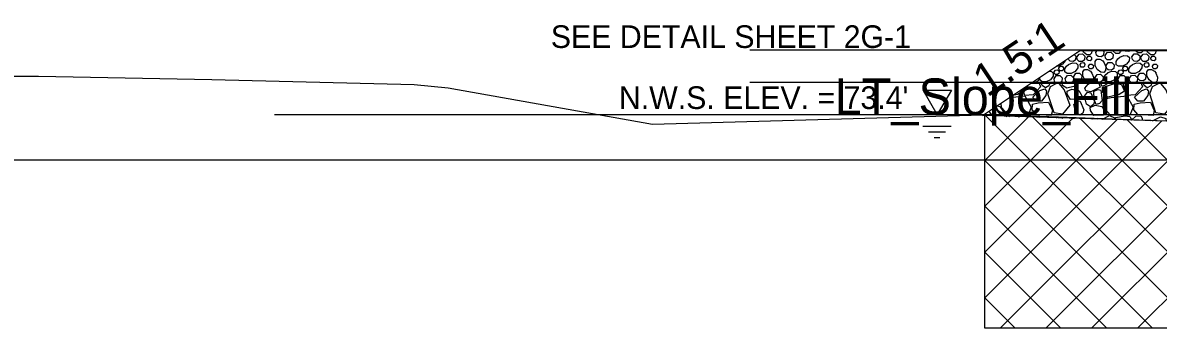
# Model space of a CAD drawing. Extents: x -14026 to 1303, y -10 to 9533.
# Drawn here: x 79.43 to 114.52, y 5494.8 to 5504.24 of the extents above; entities that cross this region are included whole.
import ezdxf

# ---------------------------------------------------------------- set-up
doc = ezdxf.new("R2010")
doc.units = 0
for name, color, linetype in [('Exist Cross Section Cell', 7, 'Continuous'), ('Exist XS Ground Line', 7, 'Continuous'), ('Old_Level_10', 7, 'Continuous'), ('Prop XS Side Slope Text', 7, 'Continuous'), ('Scratch_Level_0', 7, 'Continuous'), ('Scratch_Level_1', 7, 'Continuous'), ('Scratch_Level_3', 7, 'Continuous'), ('Scratch_Level_5', 7, 'Continuous')]:
    doc.layers.add(name, color=color, linetype=linetype)

msp = doc.modelspace()

# ---------------------------------------------------------------- linework, layer by layer
at = {"layer": 'Exist Cross Section Cell'}
msp.add_line((0, 5500), (150, 5500), dxfattribs=at)
at = {"layer": 'Exist XS Ground Line'}
msp.add_lwpolyline([(74.676, 5502.587), (79.917, 5502.591), (85.277, 5502.49), (91.527, 5502.332), (92.58, 5502.233), (98.893, 5501.11), (109.468, 5501.405), (116.444, 5501.148)], dxfattribs=at)
at = {"layer": 'Old_Level_10'}
for p, q in [((112.594, 5503.324), (112.627, 5503.371)), ((110.589, 5502.37), (125.871, 5502.37)), ((110.308, 5502.183), (110.333, 5502.127)), ((112.62, 5501.303), (112.641, 5501.263)), ((114.022, 5501.291), (114.021, 5501.221)), ((112.485, 5501.268), (112.565, 5501.282)), ((113.695, 5501.248), (113.675, 5501.232))]:
    msp.add_line(p, q, dxfattribs=at)
msp.add_lwpolyline([(116.444, 5501.148), (109.089, 5501.37), (112.089, 5503.37), (127.449, 5503.396), (125.911, 5502.396), (124.17, 5501.35)], close=True, dxfattribs=at)
for points in [[(111.65, 5503.077), (111.65, 5503.067), (111.566, 5502.96), (111.437, 5502.896), (111.376, 5502.895)], [(111.926, 5503.261), (111.979, 5503.206), (111.968, 5503.098), (111.902, 5503.043), (111.796, 5503.05), (111.746, 5503.099), (111.739, 5503.137)], [(112.036, 5503.335), (112.011, 5503.309), (111.997, 5503.309)], [(112.007, 5503.178), (112.074, 5503.273), (112.181, 5503.279), (112.256, 5503.202), (112.245, 5503.094), (112.179, 5503.039), (112.073, 5503.046), (112.023, 5503.095), (112.007, 5503.178)], [(112.468, 5503.371), (112.462, 5503.303), (112.41, 5503.248), (112.316, 5503.249), (112.209, 5503.333), (112.191, 5503.37)], [(112.313, 5503.148), (112.353, 5503.206), (112.417, 5503.209), (112.462, 5503.163), (112.456, 5503.098), (112.416, 5503.065), (112.352, 5503.069), (112.322, 5503.098), (112.313, 5503.148)], [(112.851, 5503.003), (112.901, 5502.877), (112.891, 5502.762), (112.839, 5502.707), (112.745, 5502.709), (112.639, 5502.792), (112.574, 5502.921), (112.572, 5503.042), (112.621, 5503.11), (112.717, 5503.117), (112.804, 5503.061), (112.854, 5502.998)], [(112.822, 5503.371), (112.844, 5503.349), (112.833, 5503.24), (112.767, 5503.185), (112.661, 5503.193), (112.611, 5503.241), (112.594, 5503.324)], [(112.878, 5503.229), (112.946, 5503.325), (113.053, 5503.331), (113.128, 5503.254), (113.117, 5503.145), (113.051, 5503.09), (112.945, 5503.098), (112.895, 5503.146), (112.879, 5503.229)], [(113.361, 5503.372), (113.359, 5503.347), (113.307, 5503.292), (113.213, 5503.294), (113.114, 5503.372)], [(113.334, 5503.173), (113.46, 5503.223), (113.575, 5503.213), (113.63, 5503.161), (113.628, 5503.067), (113.545, 5502.96), (113.416, 5502.896), (113.295, 5502.894), (113.226, 5502.942), (113.22, 5503.039), (113.275, 5503.126), (113.339, 5503.176)], [(113.634, 5503.373), (113.612, 5503.354), (113.506, 5503.362), (113.495, 5503.372)], [(113.709, 5503.182), (113.776, 5503.277), (113.883, 5503.284), (113.958, 5503.206), (113.947, 5503.098), (113.881, 5503.043), (113.775, 5503.05), (113.725, 5503.099), (113.709, 5503.182)], [(114.043, 5503.373), (114.042, 5503.364), (113.99, 5503.309), (113.896, 5503.31), (113.816, 5503.373)], [(113.985, 5503.178), (114.053, 5503.273), (114.16, 5503.279), (114.235, 5503.202), (114.224, 5503.094), (114.157, 5503.039), (114.051, 5503.046), (114.002, 5503.095), (113.985, 5503.178)], [(114.447, 5503.374), (114.441, 5503.303), (114.388, 5503.248), (114.295, 5503.249), (114.188, 5503.333), (114.168, 5503.374)], [(114.291, 5503.148), (114.332, 5503.206), (114.396, 5503.209), (114.441, 5503.163), (114.434, 5503.098), (114.394, 5503.065), (114.331, 5503.069), (114.301, 5503.098), (114.291, 5503.148)], [(111.142, 5502.739), (111.218, 5502.732), (111.273, 5502.68), (111.271, 5502.586), (111.188, 5502.48), (111.059, 5502.415), (110.938, 5502.413), (110.869, 5502.462), (110.863, 5502.553)], [(111.307, 5502.719), (111.347, 5502.777), (111.412, 5502.78), (111.456, 5502.734), (111.45, 5502.669), (111.41, 5502.636), (111.347, 5502.641), (111.317, 5502.67), (111.307, 5502.719)], [(111.446, 5502.836), (111.486, 5502.893), (111.55, 5502.897), (111.595, 5502.851), (111.589, 5502.786), (111.549, 5502.753), (111.485, 5502.757), (111.455, 5502.786), (111.446, 5502.836)], [(111.745, 5502.948), (111.871, 5502.998), (111.987, 5502.988), (112.041, 5502.936), (112.04, 5502.842), (111.956, 5502.736), (111.828, 5502.671), (111.706, 5502.669), (111.638, 5502.718), (111.631, 5502.814), (111.687, 5502.901), (111.75, 5502.952)], [(112.104, 5502.946), (112.145, 5503.004), (112.209, 5503.007), (112.254, 5502.961), (112.247, 5502.896), (112.208, 5502.863), (112.144, 5502.868), (112.114, 5502.897), (112.104, 5502.946)], [(112.471, 5502.686), (112.521, 5502.56), (112.511, 5502.445), (112.459, 5502.39), (112.365, 5502.391), (112.258, 5502.475), (112.194, 5502.603), (112.192, 5502.725), (112.24, 5502.793), (112.337, 5502.8), (112.423, 5502.744), (112.474, 5502.681)], [(112.369, 5502.899), (112.41, 5502.957), (112.474, 5502.96), (112.519, 5502.914), (112.512, 5502.849), (112.473, 5502.816), (112.409, 5502.82), (112.379, 5502.849), (112.369, 5502.899)], [(112.955, 5502.692), (113.081, 5502.742), (113.197, 5502.732), (113.252, 5502.68), (113.25, 5502.586), (113.167, 5502.48), (113.038, 5502.415), (112.916, 5502.413), (112.848, 5502.462), (112.842, 5502.558), (112.897, 5502.645), (112.96, 5502.695)], [(112.908, 5502.915), (112.976, 5503.01), (113.083, 5503.016), (113.158, 5502.939), (113.147, 5502.831), (113.08, 5502.775), (112.974, 5502.783), (112.925, 5502.831), (112.908, 5502.915)], [(113.286, 5502.719), (113.326, 5502.777), (113.39, 5502.78), (113.435, 5502.734), (113.429, 5502.669), (113.389, 5502.636), (113.325, 5502.641), (113.295, 5502.67), (113.286, 5502.719)], [(113.424, 5502.836), (113.465, 5502.893), (113.529, 5502.897), (113.574, 5502.851), (113.567, 5502.786), (113.528, 5502.753), (113.464, 5502.757), (113.434, 5502.786), (113.424, 5502.836)], [(113.724, 5502.948), (113.85, 5502.998), (113.965, 5502.988), (114.02, 5502.936), (114.018, 5502.842), (113.935, 5502.736), (113.806, 5502.671), (113.685, 5502.669), (113.617, 5502.718), (113.61, 5502.814), (113.666, 5502.901), (113.729, 5502.952)], [(114.083, 5502.946), (114.123, 5503.004), (114.188, 5503.007), (114.233, 5502.961), (114.226, 5502.896), (114.186, 5502.863), (114.123, 5502.868), (114.093, 5502.897), (114.083, 5502.946)], [(114.45, 5502.686), (114.499, 5502.56), (114.489, 5502.445), (114.437, 5502.39), (114.344, 5502.391), (114.237, 5502.475), (114.173, 5502.603), (114.17, 5502.725), (114.219, 5502.793), (114.316, 5502.8), (114.402, 5502.744), (114.453, 5502.681)], [(114.348, 5502.899), (114.388, 5502.957), (114.453, 5502.96), (114.497, 5502.914), (114.491, 5502.849), (114.451, 5502.816), (114.388, 5502.82), (114.358, 5502.849), (114.348, 5502.899)], [(110.846, 5502.371), (110.885, 5502.263), (110.658, 5502.01), (110.395, 5501.993), (110.336, 5502.201)], [(110.835, 5502.534), (110.827, 5502.461), (110.761, 5502.406), (110.655, 5502.413), (110.655, 5502.414)], [(111.035, 5502.226), (110.938, 5502.303), (110.913, 5502.371)], [(111.17, 5502.371), (111.145, 5502.286), (111.035, 5502.226)], [(111.447, 5502.363), (111.611, 5502.17), (111.793, 5501.689), (111.566, 5501.411), (111.302, 5501.457), (111.109, 5502.043), (111.194, 5502.272), (111.388, 5502.371)], [(111.302, 5502.509), (111.37, 5502.605), (111.477, 5502.611), (111.552, 5502.534), (111.541, 5502.425), (111.474, 5502.37), (111.368, 5502.378), (111.319, 5502.426), (111.302, 5502.509)], [(112.031, 5502.373), (111.918, 5502.267), (111.701, 5502.214), (111.56, 5502.296), (111.554, 5502.372)], [(111.649, 5502.513), (111.716, 5502.609), (111.824, 5502.615), (111.898, 5502.538), (111.888, 5502.429), (111.821, 5502.374), (111.715, 5502.382), (111.665, 5502.43), (111.649, 5502.513)], [(111.91, 5502.583), (111.977, 5502.679), (112.085, 5502.685), (112.159, 5502.608), (112.148, 5502.499), (112.082, 5502.444), (111.976, 5502.452), (111.926, 5502.5), (111.91, 5502.583)], [(112.683, 5502.374), (112.725, 5502.248), (112.438, 5502.106), (112.286, 5502.137), (112.251, 5502.218)], [(112.251, 5502.218), (112.351, 5502.34), (112.395, 5502.373)], [(112.568, 5502.545), (112.635, 5502.64), (112.742, 5502.646), (112.817, 5502.569), (112.806, 5502.461), (112.74, 5502.406), (112.634, 5502.413), (112.584, 5502.462), (112.568, 5502.545)], [(112.791, 5502.265), (112.75, 5502.358), (112.742, 5502.374)], [(112.959, 5502.374), (112.901, 5502.326), (112.791, 5502.265)], [(113.481, 5502.127), (113.316, 5502.026), (112.963, 5501.943), (112.807, 5502.087), (112.801, 5502.237), (113.202, 5502.372), (113.391, 5502.33), (113.481, 5502.127)], [(113.281, 5502.509), (113.348, 5502.605), (113.456, 5502.611), (113.53, 5502.534), (113.519, 5502.425), (113.453, 5502.37), (113.347, 5502.378), (113.297, 5502.426), (113.281, 5502.509)], [(113.991, 5502.376), (114.033, 5502.263), (113.805, 5502.01), (113.543, 5501.993), (113.434, 5502.375)], [(113.628, 5502.513), (113.695, 5502.609), (113.803, 5502.615), (113.877, 5502.538), (113.866, 5502.429), (113.8, 5502.374), (113.694, 5502.382), (113.644, 5502.43), (113.628, 5502.513)], [(113.889, 5502.583), (113.956, 5502.679), (114.063, 5502.685), (114.138, 5502.608), (114.127, 5502.499), (114.061, 5502.444), (113.955, 5502.452), (113.905, 5502.5), (113.889, 5502.583)], [(114.183, 5502.226), (114.086, 5502.303), (114.059, 5502.376)], [(114.319, 5502.376), (114.293, 5502.286), (114.183, 5502.226)], [(114.594, 5502.363), (114.758, 5502.17), (114.941, 5501.689), (114.714, 5501.411), (114.45, 5501.457), (114.257, 5502.043), (114.341, 5502.272), (114.546, 5502.377)], [(110.333, 5502.127), (110.168, 5502.026), (110.022, 5501.992)], [(111.073, 5502.121), (111.049, 5501.99), (110.915, 5501.821), (110.739, 5501.812), (110.641, 5501.942), (110.862, 5502.149), (111.014, 5502.194), (111.073, 5502.121)], [(111.708, 5502.128), (111.855, 5502.19), (112.064, 5502.149), (112.164, 5501.984), (112.112, 5501.888), (111.812, 5501.87), (111.712, 5502.034), (111.708, 5502.128)], [(112.427, 5501.643), (112.305, 5501.725), (112.239, 5501.967), (112.34, 5502.09), (112.435, 5502.075), (112.552, 5501.804), (112.519, 5501.709), (112.427, 5501.643)], [(112.601, 5501.713), (112.54, 5501.866), (112.534, 5502.121), (112.668, 5502.181), (112.752, 5502.157), (112.791, 5501.834), (112.706, 5501.742), (112.601, 5501.713)], [(114.22, 5502.121), (114.197, 5501.99), (114.063, 5501.821), (113.886, 5501.812), (113.789, 5501.942), (114.01, 5502.149), (114.162, 5502.194), (114.22, 5502.121)], [(109.535, 5501.668), (109.63, 5501.649), (109.736, 5501.484), (109.684, 5501.388), (109.384, 5501.37), (109.293, 5501.506)], [(109.937, 5501.935), (110.4, 5501.978), (110.596, 5501.636), (110.499, 5501.388), (109.899, 5501.389), (109.677, 5501.617), (109.668, 5501.756)], [(110.634, 5501.719), (110.814, 5501.763), (111.132, 5501.783), (111.249, 5501.525), (111.217, 5501.379), (110.747, 5501.404), (110.623, 5501.549), (110.634, 5501.719)], [(112.098, 5501.385), (111.975, 5501.467), (111.909, 5501.709), (112.011, 5501.831), (112.105, 5501.817), (112.222, 5501.546), (112.189, 5501.451), (112.098, 5501.385)], [(112.422, 5501.622), (112.569, 5501.691), (112.777, 5501.649), (112.884, 5501.484), (112.832, 5501.388), (112.532, 5501.37), (112.426, 5501.528), (112.422, 5501.622)], [(112.808, 5501.879), (113.062, 5501.933), (113.548, 5501.978), (113.743, 5501.636), (113.647, 5501.388), (113.047, 5501.389), (112.825, 5501.617), (112.808, 5501.879)], [(113.782, 5501.719), (113.962, 5501.763), (114.28, 5501.783), (114.397, 5501.525), (114.365, 5501.379), (113.895, 5501.404), (113.77, 5501.549), (113.782, 5501.719)], [(109.824, 5501.348), (109.866, 5501.37), (109.921, 5501.345)], [(110.197, 5501.337), (110.349, 5501.365), (110.5, 5501.34), (110.507, 5501.327)], [(110.649, 5501.323), (110.686, 5501.357), (110.835, 5501.359), (110.86, 5501.317)], [(111.373, 5501.301), (111.441, 5501.334), (111.577, 5501.295)], [(111.885, 5501.286), (112, 5501.307), (112.151, 5501.282), (112.154, 5501.278)], [(112.802, 5501.258), (113.013, 5501.37), (113.166, 5501.301), (113.168, 5501.247)], [(113.204, 5501.246), (113.198, 5501.309), (113.496, 5501.365), (113.648, 5501.34), (113.695, 5501.248)], [(113.698, 5501.231), (113.833, 5501.357), (113.982, 5501.359), (114.022, 5501.291)], [(114.34, 5501.212), (114.588, 5501.334), (114.759, 5501.285), (114.766, 5501.199)], [(114.064, 5501.22), (114.072, 5501.23), (114.271, 5501.245), (114.28, 5501.214)]]:
    msp.add_lwpolyline(points, dxfattribs=at)
at = {"layer": 'Prop XS Side Slope Text'}
for p, q in [((107.242, 5501.046), (108.117, 5501.046)), ((107.417, 5500.871), (107.942, 5500.871)), ((107.592, 5500.696), (107.767, 5500.696))]:
    msp.add_line(p, q, dxfattribs=at)
msp.add_lwpolyline([(107.255, 5502.159), (108.13, 5502.159), (107.692, 5501.4)], close=True, dxfattribs=at)
at = {"layer": 'Scratch_Level_1'}
msp.add_line((87.209, 5501.4), (131.749, 5501.4), dxfattribs=at)
at = {"layer": 'Scratch_Level_3'}
for p, q in [((127.449, 5503.396), (101.898, 5503.396)), ((125.911, 5502.396), (101.898, 5502.396)), ((109.161, 5501.396), (101.898, 5501.396))]:
    msp.add_line(p, q, dxfattribs=at)
at = {"layer": 'Scratch_Level_5'}
for p, q in [((109.161, 5501.396), (115.757, 5494.8)), ((109.161, 5499.982), (110.529, 5501.35)), ((109.161, 5498.568), (111.896, 5501.303)), ((110.625, 5501.346), (117.171, 5494.8)), ((112.089, 5501.297), (118.586, 5494.8)), ((109.161, 5497.153), (113.264, 5501.257)), ((109.161, 5495.739), (114.632, 5501.21)), ((109.636, 5494.8), (116, 5501.164)), ((111.05, 5494.8), (117.424, 5501.174)), ((112.464, 5494.8), (118.876, 5501.212)), ((113.553, 5501.247), (120, 5494.8)), ((113.879, 5494.8), (120.329, 5501.25)), ((109.161, 5499.982), (114.343, 5494.8)), ((109.161, 5498.568), (112.929, 5494.8)), ((109.161, 5497.153), (111.515, 5494.8)), ((109.161, 5495.739), (110.1, 5494.8))]:
    msp.add_line(p, q, dxfattribs=at)
msp.add_lwpolyline([(124.17, 5501.35), (124.17, 5494.8), (109.161, 5494.8), (109.161, 5501.396), (109.468, 5501.405), (116.444, 5501.148)], close=True, dxfattribs=at)

# ---------------------------------------------------------------- texts
at = {"layer": 'Old_Level_10'}
msp.add_text('SEE DETAIL SHEET 2G-1', height=0.7, dxfattribs=at).set_placement((95.749, 5503.46))
at = {"layer": 'Prop XS Side Slope Text'}
msp.add_text('1.5:1', height=1, rotation=33.6901, dxfattribs=at).set_placement((109.237, 5501.919))
msp.add_text("N.W.S. ELEV. = 73.4'", height=0.7, dxfattribs=at).set_placement((97.853, 5501.575))
at = {"layer": 'Scratch_Level_0'}
msp.add_text('LT_Slope_Fill', height=1.125, dxfattribs=at).set_placement((104.52, 5501.396))

doc.saveas('drawing.dxf')
